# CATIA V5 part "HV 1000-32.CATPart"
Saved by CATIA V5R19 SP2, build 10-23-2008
Part number: HV 1000-32
Bounding box of the stored display mesh (mm): x -24.865 to 24.865, y -24.997 to 24.997, z 0 to 121
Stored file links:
  C:\Users\Bora\Desktop\3D KATI MODEL- CATIA PART\HV serisi\HV 1000\HV 1000-32.CATPart
  C:\Program Files\Dassault Systemes\B19\intel_a\reffiles\standard\MetricThickPitch.txt
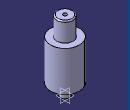
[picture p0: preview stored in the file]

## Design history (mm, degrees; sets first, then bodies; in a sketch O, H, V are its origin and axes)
Body1 (main body)
  Sketch1 on yz-plane, origin (0, 0, 0), H (0, 1, 0), V (0, 0, 1)
    point P1 (14, 119)
    point P3 (14, 119)
    point P8 (8, 17)
    point P10 (8, 1)
    point P11 (8, 17)
    point P12 (8, 1)
    arc A1 centre (12, 119) radius 2 from (14, 119) to (12, 121) ccw
    line L1 (14, 119) -> (14, 88)
    arc A2 centre (8, 18) radius 1 from (8, 19) to (8, 17) ccw
    line L2 (7, 0) -> (8, 1)
    line L3 (8, 17) -> (8, 1)
    line L4 (12, 121) -> (0, 121)
    point P13 (0, 121)
    line L5 (14, 88) -> (25, 88)
    line L6 (8, 19) -> (25, 19)
    line L7 (7, 0) -> (0, 0)
    line L8 (25, 88) -> (25, 19)
    tangency: L4 A1, L6 A2
    coincidence: P13 V, P1 P3, P8 P11, P10 P12
    horizontal: L5 H, L7 H
    vertical: L8 V
  Shaft1: profile Sketch1, axis Sketch1.V, angle 360
  Sketch2 on face of Shaft1 from Sketch1.L7, origin (0, 0, 0), H (1, 0, 0), V (0, -1, 0)
    point P1 (0, 0)
  Hole1: placed by Sketch2, at (0, 0, 0) direction (0, 0, 1), diameter 13.835, depth 19, threaded "M16", thread diameter 16, thread depth 19, pitch 2
  Sketch3 on face of Shaft1 from Sketch1.L4, origin (0, 0, 121), H (1, 0, 0), V (0, 1, 0)
    point P1 (0, 0)
  Hole2: placed by Sketch3, at (0, 0, 121) direction (0, 0, -1), diameter 6.647, depth 15, threaded "M8", thread diameter 8, thread depth 15, pitch 1.25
